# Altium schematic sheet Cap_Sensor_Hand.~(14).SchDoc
size A3
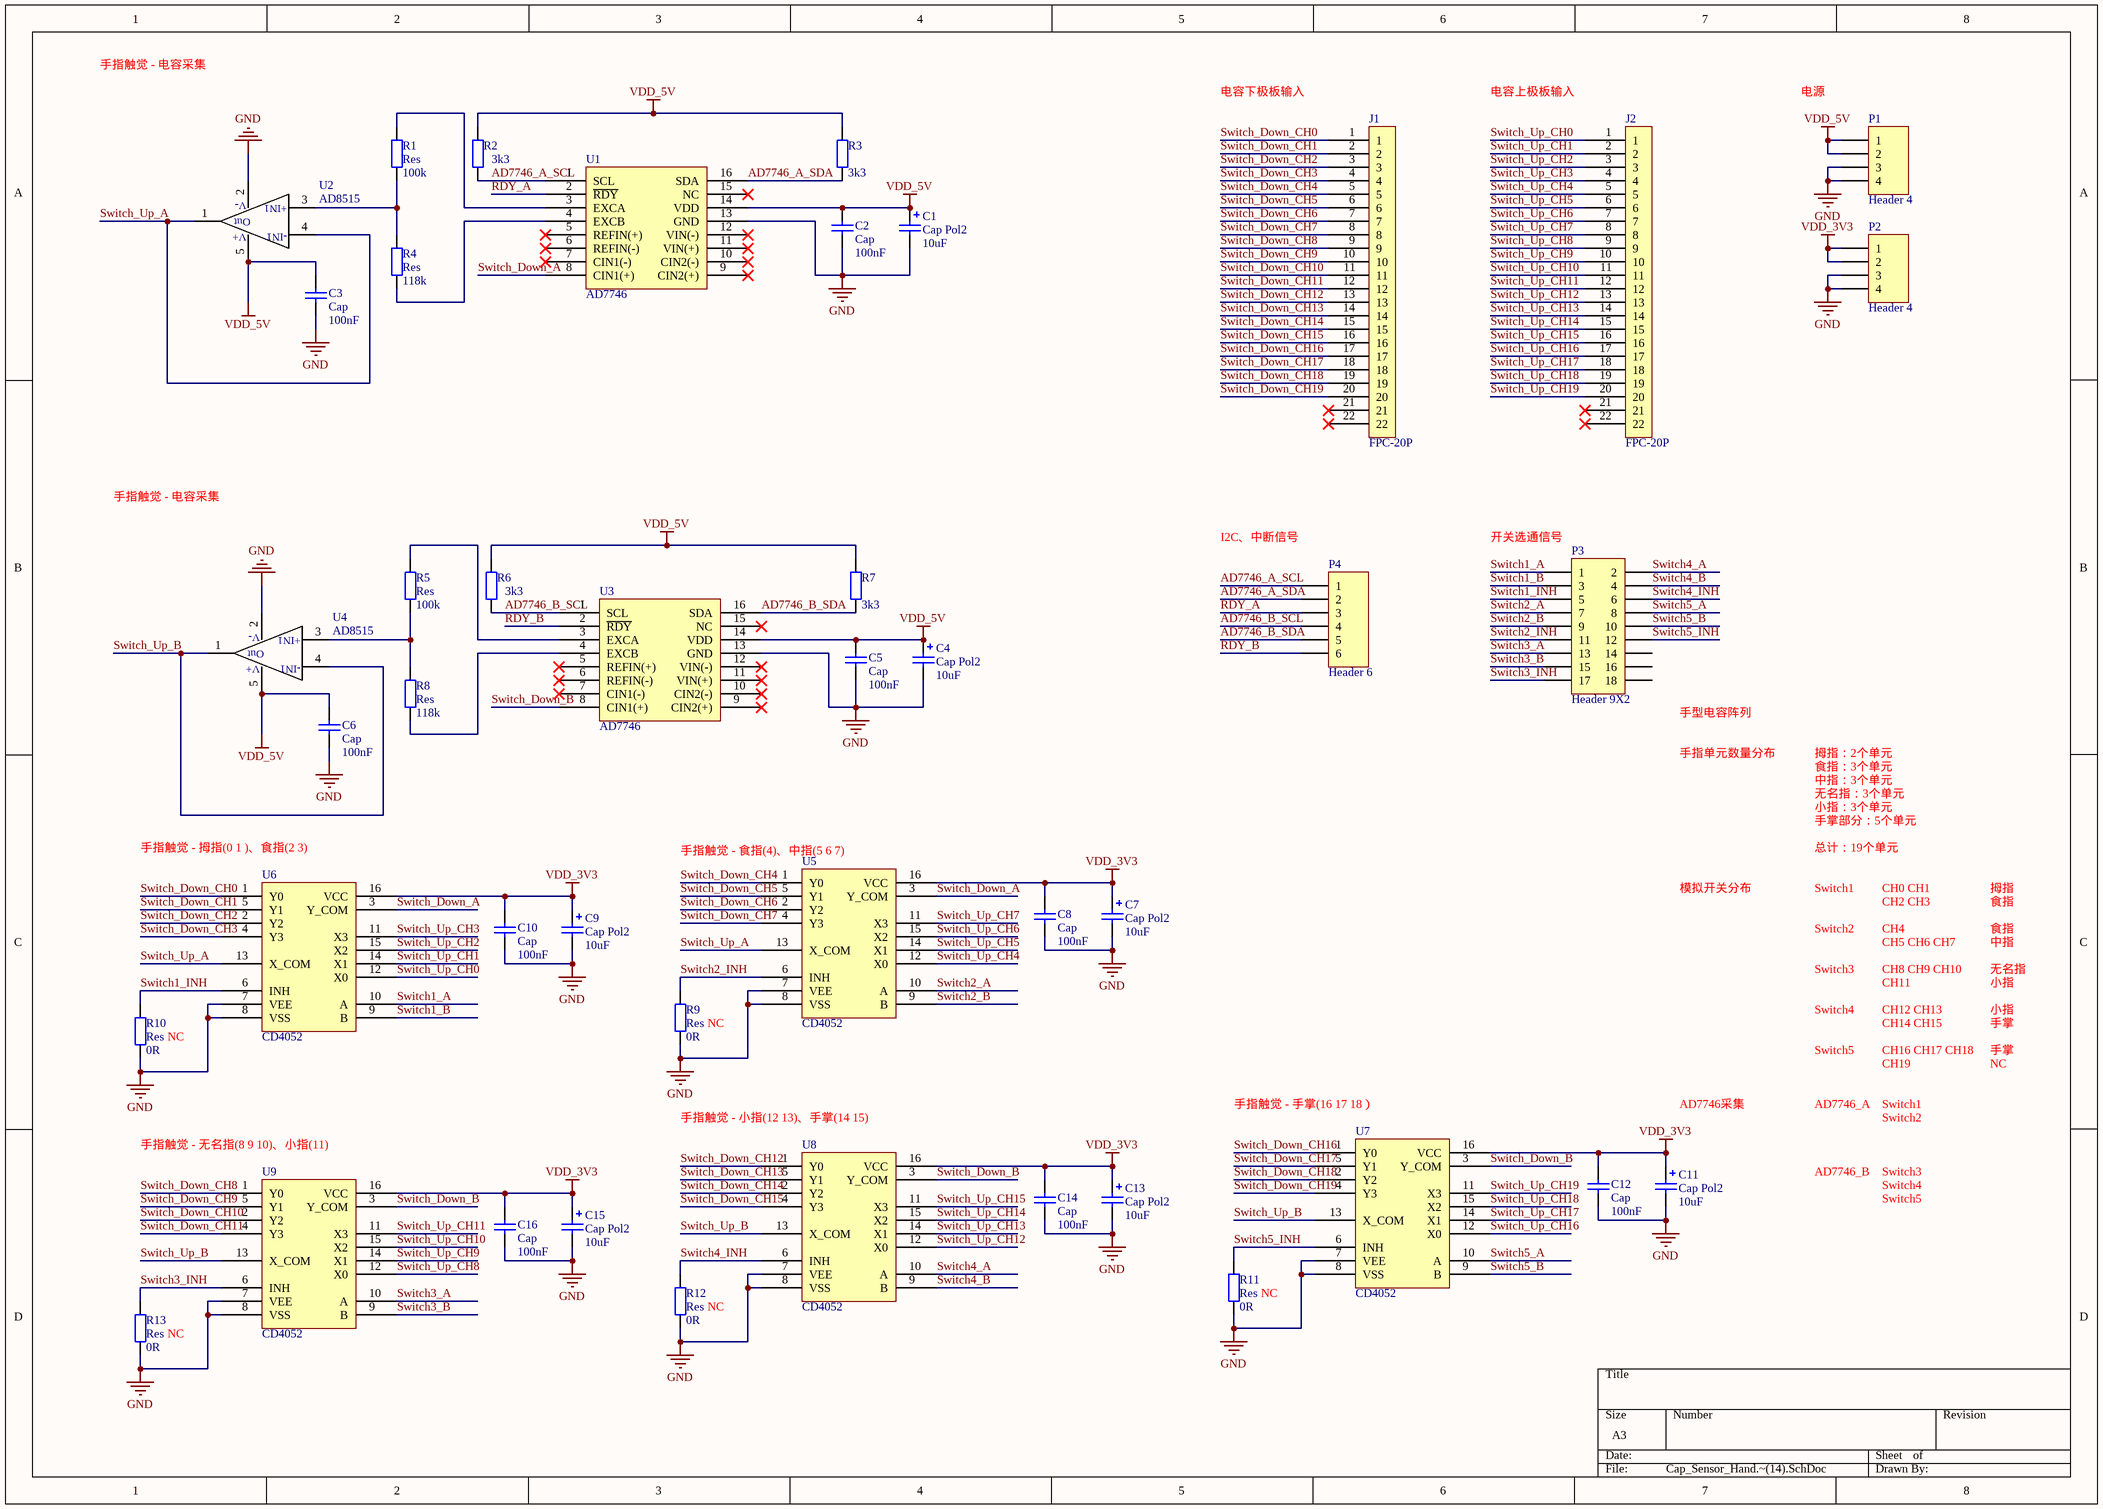
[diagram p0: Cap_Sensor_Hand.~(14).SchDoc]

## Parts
C1  Cap Pol2  value 10uF  [Cap-TA]
C2  Cap  value 100nF  [0805C]
C3  Cap  value 100nF  [0805C]
C4  Cap Pol2  value 10uF  [Cap-TA]
C5  Cap  value 100nF  [0805C]
C6  Cap  value 100nF  [0805C]
C7  Cap Pol2  value 10uF  [Cap-TA]
C8  Cap  value 100nF  [0805C]
C9  Cap Pol2  value 10uF  [Cap-TA]
C10  Cap  value 100nF  [0805C]
C11  Cap Pol2  value 10uF  [Cap-TA]
C12  Cap  value 100nF  [0805C]
C13  Cap Pol2  value 10uF  [Cap-TA]
C14  Cap  value 100nF  [0805C]
C15  Cap Pol2  value 10uF  [Cap-TA]
C16  Cap  value 100nF  [0805C]
J1  FPC-20P  [FPC20-0.5]
J2  FPC-20P  [FPC20-0.5]
P1  Header 4  [HDR1X4]
P2  Header 4  [HDR1X4]
P3  Header 9X2  [HDR2X9]
P4  Header 6  [HDR1X6]
R1  Res  value 100k  [0805R]
R2  value 3k3  [0805R]  (hidden comment: Res)
R3  value 3k3  [0805R]  (hidden comment: Res)
R4  Res  value 118k  [0805R]
R5  Res  value 100k  [0805R]
R6  value 3k3  [0805R]  (hidden comment: Res)
R7  value 3k3  [0805R]  (hidden comment: Res)
R8  Res  value 118k  [0805R]
R9  Res  value 0R  [0805R]
R10  Res  value 0R  [0805R]
R11  Res  value 0R  [0805R]
R12  Res  value 0R  [0805R]
R13  Res  value 0R  [0805R]
U1  AD7746  [TSSOP16]
U2  AD8515  [sot23-5]
U3  AD7746  [TSSOP16]
U4  AD8515  [sot23-5]
U5  CD4052  [sop16]
U6  CD4052  [SOP16]
U7  CD4052  [sop16]
U8  CD4052  [sop16]
U9  CD4052  [sop16]

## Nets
GND: C1.2 C2.1 C3.1 C4.2 C5.1 C6.1 C7.2 C8.1 C9.2 C10.1 C11.2 C12.1 C13.2 C14.1 C15.2 C16.1 P1.3 P1.4 P2.3 P2.4 R9.2 R10.2 R11.2 R12.2 R13.2 U1.13(GND) U2.2(V-) U3.13(GND) U4.2(V-) U5.7(VEE) U5.8(VSS) U6.7(VEE) U6.8(VSS) U7.7(VEE) U7.8(VSS) U8.7(VEE) U8.8(VSS) U9.7(VEE) U9.8(VSS)
VDD_3V3: C7.1 C8.2 C9.1 C10.2 C11.1 C12.2 C13.1 C14.2 C15.1 C16.2 P2.1 P2.2 U5.16(VCC) U6.16(VCC) U7.16(VCC) U8.16(VCC) U9.16(VCC)
VDD_5V: C1.1 C2.2 C3.2 C4.1 C5.2 C6.2 P1.1 P1.2 R2.2 R3.2 R6.2 R7.2 U1.14(VDD) U2.5(V+) U3.14(VDD) U4.5(V+)
AD7746_A_SCL: P4.1 R2.1 U1.1(SCL)
AD7746_A_SDA: P4.2 R3.1 U1.16(SDA)
AD7746_B_SCL: P4.4 R6.1 U3.1(SCL)
AD7746_B_SDA: P4.5 R7.1 U3.16(SDA)
RDY_A: P4.3 U1.2(~{RDY})
RDY_B: P4.6 U3.2(~{RDY})
Switch1_A: P3.1 U6.10(A)
Switch1_B: P3.3 U6.9(B)
Switch1_INH: P3.5 R10.1 U6.6(INH)
Switch2_A: P3.7 U5.10(A)
Switch2_B: P3.9 U5.9(B)
Switch2_INH: P3.11 R9.1 U5.6(INH)
Switch3_A: P3.13 U9.10(A)
Switch3_B: P3.15 U9.9(B)
Switch3_INH: P3.17 R13.1 U9.6(INH)
Switch4_A: P3.2 U8.10(A)
Switch4_B: P3.4 U8.9(B)
Switch4_INH: P3.6 R12.1 U8.6(INH)
Switch5_A: P3.8 U7.10(A)
Switch5_B: P3.10 U7.9(B)
Switch5_INH: P3.12 R11.1 U7.6(INH)
Switch_Down_A: U1.8(CIN1(+)) U5.3(Y_COM) U6.3(Y_COM)
Switch_Down_B: U3.8(CIN1(+)) U7.3(Y_COM) U8.3(Y_COM) U9.3(Y_COM)
Switch_Down_CH0: J1.1 U6.1(Y0)
Switch_Down_CH1: J1.2 U6.5(Y1)
Switch_Down_CH2: J1.3 U6.2(Y2)
Switch_Down_CH3: J1.4 U6.4(Y3)
Switch_Down_CH4: J1.5 U5.1(Y0)
Switch_Down_CH5: J1.6 U5.5(Y1)
Switch_Down_CH6: J1.7 U5.2(Y2)
Switch_Down_CH7: J1.8 U5.4(Y3)
Switch_Down_CH8: J1.9 U9.1(Y0)
Switch_Down_CH9: J1.10 U9.5(Y1)
Switch_Down_CH10: J1.11 U9.2(Y2)
Switch_Down_CH11: J1.12 U9.4(Y3)
Switch_Down_CH12: J1.13 U8.1(Y0)
Switch_Down_CH13: J1.14 U8.5(Y1)
Switch_Down_CH14: J1.15 U8.2(Y2)
Switch_Down_CH15: J1.16 U8.4(Y3)
Switch_Down_CH16: J1.17 U7.1(Y0)
Switch_Down_CH17: J1.18 U7.5(Y1)
Switch_Down_CH18: J1.19 U7.2(Y2)
Switch_Down_CH19: J1.20 U7.4(Y3)
Switch_Up_A: U2.1(Out1) U2.4(-IN) U5.13(X_COM) U6.13(X_COM)
Switch_Up_B: U4.1(Out1) U4.4(-IN) U7.13(X_COM) U8.13(X_COM) U9.13(X_COM)
Switch_Up_CH0: J2.1 U6.12(X0)
Switch_Up_CH1: J2.2 U6.14(X1)
Switch_Up_CH2: J2.3 U6.15(X2)
Switch_Up_CH3: J2.4 U6.11(X3)
Switch_Up_CH4: J2.5 U5.12(X0)
Switch_Up_CH5: J2.6 U5.14(X1)
Switch_Up_CH6: J2.7 U5.15(X2)
Switch_Up_CH7: J2.8 U5.11(X3)
Switch_Up_CH8: J2.9 U9.12(X0)
Switch_Up_CH9: J2.10 U9.14(X1)
Switch_Up_CH10: J2.11 U9.15(X2)
Switch_Up_CH11: J2.12 U9.11(X3)
Switch_Up_CH12: J2.13 U8.12(X0)
Switch_Up_CH13: J2.14 U8.14(X1)
Switch_Up_CH14: J2.15 U8.15(X2)
Switch_Up_CH15: J2.16 U8.11(X3)
Switch_Up_CH16: J2.17 U7.12(X0)
Switch_Up_CH17: J2.18 U7.14(X1)
Switch_Up_CH18: J2.19 U7.15(X2)
Switch_Up_CH19: J2.20 U7.11(X3)
NetR1_1: R1.1 U1.3(EXCA)
NetR1_2: R1.2 R4.1 U2.3(+IN)
NetR4_2: R4.2 U1.4(EXCB)
NetR5_1: R5.1 U3.3(EXCA)
NetR5_2: R5.2 R8.1 U4.3(+IN)
NetR8_2: R8.2 U3.4(EXCB)

Not connected (* = marked no-connect by the designer): J1 21* 22*; J2 21* 22*; P3 14 16 18; U1 5(REFIN(+))* 6(REFIN(-))* 7(CIN1(-))* 9(CIN2(+))* 10(CIN2(-))* 11(VIN(+))* 12(VIN(-))* 15(NC)*; U3 5(REFIN(+))* 6(REFIN(-))* 7(CIN1(-))* 9(CIN2(+))* 10(CIN2(-))* 11(VIN(+))* 12(VIN(-))* 15(NC)*

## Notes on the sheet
- 手指触觉 - 电容采集
- 电容下极板输入
- 电容上极板输入
- 电源
- I2C、中断信号
- (near P3) 开关选通信号
- 手型电容阵列
- 手指单元数量分布
- 拇指：2个单元
- 食指：3个单元
- 中指：3个单元
- (near U6) 手指触觉 - 拇指(0 1 )、食指(2 3)
- (near U5) 手指触觉 - 食指(4)、中指(5 6 7)
- 无名指：3个单元
- 小指：3个单元
- 手掌部分：5个单元
- 总计：19个单元
- 模拟开关分布
- Switch1
- CH0 CH1
- CH2 CH3
- 拇指
- 食指
- Switch2
- Switch3
- CH4
- CH5 CH6 CH7
- CH8 CH9 CH10
- CH11
- 中指
- 无名指
- 小指
- (near R10) NC
- (near R9) NC
- Switch4
- Switch5
- CH12 CH13
- CH14 CH15
- CH16 CH17 CH18
- 手掌
- (near U8) 手指触觉 - 小指(12 13)、手掌(14 15)
- (near U7) 手指触觉 - 手掌(16 17 18）
- AD7746采集
- AD7746_A
- CH19
- NC
- (near U9) 手指触觉 - 无名指(8 9 10)、小指(11)
- AD7746_B
- (near R12) NC
- (near R11) NC
- (near R13) NC

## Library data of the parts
C1 C4 C7 C9 C11 C13 C15 = Cap Pol2: Polarized Capacitor (Axial)
C2 C3 C5 C6 C8 C10 C12 C14 C16 = Cap: Capacitor
J1 J2 = FPC_20P
P1 P2 = Header 4: Header, 4-Pin
P3 = Header 9X2: Header, 9-Pin, Dual row
P4 = Header 6: Header, 6-Pin
R1-R13 = Res: Resistor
